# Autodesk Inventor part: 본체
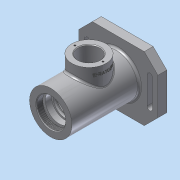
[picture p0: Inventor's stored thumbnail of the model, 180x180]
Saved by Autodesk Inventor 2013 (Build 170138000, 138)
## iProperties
Created: 2017-10
Part Number: 본체
Material: 알루미늄 6061
Document SubType Name: Modeling
Designer: Administrator
Density: 2.71 g/cm^3
Mass: 789.707 g
Surface Area: 662.634 cm^2
Volume: 291.405 cm^3
Author: Administrator
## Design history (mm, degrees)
sketch "스케치2"
  geometry: L1 (0, 0)-(99, 0); L2 (0, 0)-(0, 31); L3 (0, 31)-(99, 31); L4 (99, 31)-(99, 0)
  constraints: 8 end point, 3 perpendicular, 1 horizontal
  dimensions: "d0" = 99 distance of L1.start L1.end; "d2" = 62 diameter of L3 L1
revolve "회전1" sketch "스케치2" stored, may be unused: angle "d3" = 90 deg
sketch "스케치3"
  geometry: L1 (38, -47)-(-38, -47); L2 (-58, -27)-(-58, 27); L3 (-38, 47)-(38, 47); L4 (58, 27)-(58, -27); L5 (0, 0)-(-31, 0); L6 (0, 0)-(0, -31); L7 (58, -27)-(38, -47); L8 (-38, -47)-(-58, -27); L9 (-58, 27)-(-38, 47); L10 (58, 27)-(38, 47); L11 (42, -20)-(42, 20); L12 (50, -20)-(50, 20); L13 (-42, -20)-(-42, 20); L14 (-50, -20)-(-50, 20); A1 r 31 centre (0, 0) between (-31, 0) and (0, -31) reference; A2 r 4 centre (46, 20) between (50, 20) and (42, 20); A3 r 4 centre (46, -20) between (42, -20) and (50, -20); A4 r 4 centre (-46, -20) between (-50, -20) and (-42, -20); A5 r 4 centre (-46, 20) between (-42, 20) and (-50, 20); 4 further points
  constraints: 28 end point, 10 point on circle, 8 point on line, 6 symmetric about line, 4 centre point, 3 parallel, 3 perpendicular, 3 tangent, 1 equal radius, 1 horizontal, 5 other
  dimensions: "d5" = 116 distance between parallel lines of L2 L4; "d7" = 94 distance between parallel lines of L3 L1; "d8" = 20 distance of L4.end point (58, -47); "d9" = 20 distance of L1.start point (58, -47) (= d8); "d10" = 20 distance of L1.end point (-58, -47) (= d8); "d11" = 20 distance of L2.start point (-58, -47) (= d10); "d12" = 20 distance of L2.end point (-58, 47) (= d8); "d13" = 20 distance of L3.start point (-58, 47) (= d12); "d14" = 20 distance of L4.start point (58, 47) (= d8); "d15" = 20 distance of L3.end point (58, 47) (= d14); "d16" = 8 diameter of A3; "d17" = 40 distance of A2.centre A3.centre; "d18" = 92 distance of A5.centre A2.centre
extrude "돌출1" join sketch "스케치3" distance "d19" = 13; taper "d20" = 0 deg
sketch "스케치4"
  geometry: C1 r 35 at (0, 0); 1 further point
  constraints: 1 centre point, 1 coincident
  dimensions: "d21" = 70 diameter of C1
extrude "돌출2" join sketch "스케치4" distance "d23" = 3; taper "d24" = 0 deg
sketch "스케치5"
  geometry: L1 (0, -31)-(0, 31) reference; L2 (0, 31)-(99, 31) reference; L3 (99, 31)-(99, 47) reference; L4 (99, 47)-(112, 47) reference; L5 (112, 47)-(112, 35) reference; L6 (112, 35)-(115, 35) reference; L7 (115, 35)-(115, -35) reference; L8 (115, -35)-(112, -35) reference; L9 (112, -35)-(112, -47) reference; L10 (112, -47)-(99, -47) reference; L11 (99, -47)-(99, -31) reference; L12 (99, -31)-(0, -31) reference; L13 (0, 0)-(115, 0); L14 (0, -31)-(0, 31) reference; L15 (0, 21)-(9, 21); L16 (9, 21)-(9, 24); L17 (9, 24)-(12, 24); L18 (12, 24)-(12, 20); L19 (12, 20)-(21, 20); L20 (21, 20)-(21, 17.5); L21 (21, 17.5)-(24.25, 17.5); L22 (24.25, 17.5)-(24.25, 18.5); L23 (24.25, 18.5)-(26, 18.5); L24 (26, 18.5)-(26, 17.5); L25 (26, 17.5)-(36, 17.5); L26 (37, 18.5)-(37, 23); L27 (40, 26)-(72, 26); L28 (75, 23)-(75, 18.5); L29 (76, 17.5)-(85.7, 17.5); L30 (86, 17.2)-(86, 16.5); L31 (86, 16.5)-(88, 16.5); L32 (91, 13.5)-(91, 10); L33 (91, 10)-(93.7, 10); L34 (93.7, 10)-(93.7, 12.2); L35 (94, 12.5)-(100.3, 12.5); L36 (101, 12.904)-(101, 14.022); L37 (102.818, 16.779)-(115, 22); L38 (100.3, 12.5)-(101, 12.904); L39 (75, 18.5)-(76, 17.5); L40 (36, 17.5)-(37, 18.5); A1 r 3 centre (88, 13.5) between (91, 13.5) and (88, 16.5); A2 r 3 centre (104, 14.022) between (102.818, 16.779) and (101, 14.022); A3 r 0.3 centre (85.7, 17.2) between (86, 17.2) and (85.7, 17.5); A4 r 0.3 centre (94, 12.2) between (94, 12.5) and (93.7, 12.2); A5 r 3 centre (40, 23) between (40, 26) and (37, 23); A6 r 3 centre (72, 23) between (75, 23) and (72, 26); 9 further points
  constraints: 54 end point, 20 point on line, 15 parallel, 12 point on circle, 12 tangent, 7 perpendicular, 6 centre point, 3 equal radius, 1 midpoint
  dimensions: "d25" = 42 diameter of L15 L13; "d27" = 48 diameter of L17 L13; "d28" = 40 diameter of L19 L13; "d29" = 35 diameter of L21 L13; "d30" = 37 diameter of L23 L13; "d31" = 35 diameter of L25 L13; "d32" = 52 diameter of L27 L13; "d33" = 35 diameter of L29 L13; "d34" = 33 diameter of L31 L13; "d35" = 20 diameter of L33 L13; "d36" = 25 diameter of L35 L13; "d37" = 32 diameter of point (101, 16) L13; "d38" = 44 diameter of L37.end L13; "d39" = 12 distance between parallel lines of L18 L1; "d40" = 3 distance between parallel lines of L18 L16; "d41" = 21 distance between parallel lines of L20 L1; "d42" = 26 distance between parallel lines of L1 L24; "d43" = 1.75 distance between parallel lines of L24 L22; "d44" = 60 distance between parallel lines of L30 L24; "d45" = 5 distance between parallel lines of L32 L30; "d46" = 14 distance between parallel lines of L36 L7; "d47" = 7.3 distance between parallel lines of L34 L36; "d48" = 11 distance between parallel lines of L28 L30; "d49" = 11 distance between parallel lines of L24 L26; "d51" = 3 radius of A1; "d52" = 0.3 radius of A3; "d53" = 0.7 distance of L35.end point (101, 12.5); "d54" = 30 deg angle of L35 L38; "d55" = 1 distance of L28.end point (75, 17.5); "d56" = 1 distance of L29.start point (75, 17.5) (= d55); "d57" = 1 distance of L25.end point (37, 17.5) (= d55); "d58" = 1 distance of L26.start point (37, 17.5) (= d57); "d59" = 3 radius of A5
revolve "회전2" sketch "스케치5" stored, may be unused: angle "d50" = 90 deg
feature "스레드1" dims "d60" = 10, "d61" = 0
chamfer "모따기1" distance "d62" = 1; stored, may be unused: second distance "d63" = 2, angle "d64" = 45 deg
node "작업 평면2"
sketch "스케치6"
  geometry: L1 (0, 0)-(0, 115); L2 (-22, 115)-(22, 115) reference; L3 (31, 0)-(-31, 0) reference; C1 r 25 at (0, 56)
  constraints: 2 end point, 1 centre point, 1 midpoint, 1 point on line
  dimensions: "d91" = 50 diameter of C1; "d93" = 56 distance from line of L3 C1.centre
extrude "돌출3" join sketch "스케치6" stored distance "d68" = 10; taper "d69" = 0 deg
fillet "모깎기1" dims "d86" = 3
sketch "스케치10"
  geometry: C1 r 25 at (0, 0) reference; C2 r 16 at (0, 0); 1 further point
  constraints: 1 centre point, 1 coincident
  dimensions: "d94" = 32 diameter of C2
extrude "돌출5" cut sketch "스케치10" stored distance "d96" = 10; taper "d97" = 0 deg
sketch "스케치11" dims "d98" = 41
  geometry: L1 (0, 0)-(20.5, 0); C1 r 25 at (0, 0) reference; 2 further points
  constraints: 2 coincident, 2 end point, 1 horizontal, 1 horizontal alignment, 2 other
hole "구멍2" sketch "스케치11" at (20.5, 0) diameter "d100" = 2.459; stored, may be unused: countersink angle "d104" = 90 deg, drill point angle "d106" = 118 deg; dims "d101" = 6, "d102" = 4, "d103" = 2, "d105" = 8
node "작업 평면4"
sketch "스케치12"
  geometry: L1 (-15.909, -7.749)-(15.909, -7.749); L2 (15.909, -7.749)-(15.909, -12.251); L3 (15.909, -12.251)-(-15.909, -12.251); L4 (-15.909, -12.251)-(-15.909, -7.749); L5 (-15.909, -10)-(15.909, -10); L6 (0, -12.251)-(0, -7.749); L7 (-56, -78)-(-56, -16) reference; L8 (-25, 0)-(25, 0) reference; 1 further point
  constraints: 4 end point, 4 midpoint, 2 other
  dimensions: "d110" = 56 distance between parallel lines of L6 L7; "d111" = 10 distance between parallel lines of L5 L8
feature "엠보싱1" sketch "스케치12" dims "d0" = 99, "d2" = 62, "d12" = 20 (= d8), "d112" = 0.5, "d113" = 0
fillet "모깎기2" dims "d114" = 3
chamfer "모따기2" distance "d115" = 1; stored, may be unused: second distance "d116" = 2, angle "d117" = 45 deg
node "솔리드1"
pattern_circular "원형 패턴2" dims angle "d108" = 360 deg
node "절단 모서리 투영1"
other parameters: "d65" = 47
